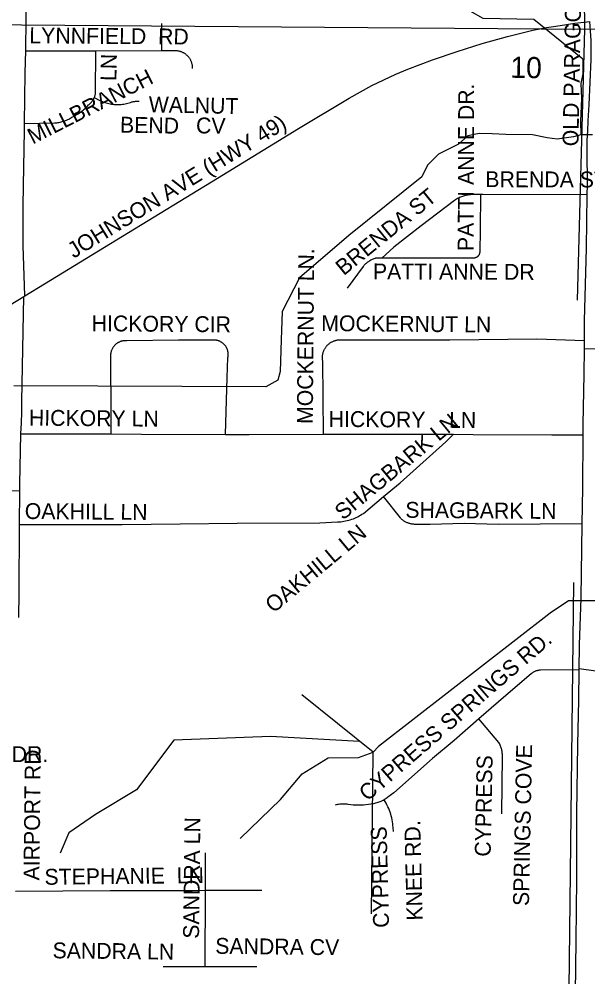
# Model space of a CAD drawing. Extents: x 1670563 to 1761545, y 515755 to 578944.
# Drawn here: x 1712453 to 1715137, y 555467 to 559991 of the extents above; entities that cross this region are included whole.
import ezdxf

# ---------------------------------------------------------------- set-up
doc = ezdxf.new("R2010")
doc.units = 0
for name, color, linetype in [('5_sectionlines', 7, 'Continuous'), ('62_text', 7, 'Continuous'), ('SHP_LINE', 7, 'Continuous'), ('STREETCL', 7, 'Continuous'), ('STRNAMES', 7, 'Continuous')]:
    doc.layers.add(name, color=color, linetype=linetype)

msp = doc.modelspace()

# ---------------------------------------------------------------- linework, layer by layer
at = {"layer": '5_sectionlines'}
msp.add_line((1715092.6, 565233.3), (1715121.2, 559943.8), dxfattribs=at)
for points in [[(1715121.2, 559943.8), (1720383.9, 560096.2), (1725635, 560117.2)], [(1677977.7, 559756.7), (1683296.8, 559793.9), (1688575.5, 559928.7), (1693867.8, 559919.3), (1699198.2, 559938), (1704504.6, 559990.6), (1709805, 559985.3), (1715121.2, 559943.8), (1715086.8, 558664.7)], [(1715069.2, 557329.6), (1715039, 554724.2), (1714928.9, 549450.5), (1714933.4, 546249.8)]]:
    msp.add_lwpolyline(points, dxfattribs=at)
at = {"layer": 'SHP_LINE'}
for points in [[(1715114, 559803), (1714883, 559990), (1714643, 559994), (1714582, 560029), (1714465, 560160), (1714343, 560203), (1714286, 560308), (1714194, 560386), (1713781, 560612)], [(1715114, 559803), (1715114, 559733), (1715105, 559688), (1715107, 559616), (1715103, 559510), (1715104, 559445)], [(1715159, 559445), (1715104, 559445), (1715069, 559435), (1714992, 559424), (1714945, 559431), (1714876, 559445), (1714751, 559446), (1714685, 559450), (1714625, 559452), (1714571, 559440), (1714527, 559401), (1714433, 559353), (1714381, 559302), (1714354, 559247), (1714009, 558970), (1713777, 558770), (1713695, 558610), (1713690, 558476), (1713685, 558327), (1713674, 558286), (1713618, 558255), (1712428, 558260)], [(1717283, 557390), (1716826, 557398), (1716048, 557390), (1715554, 557371), (1715449, 557349), (1715283, 557260), (1715184, 557243), (1715046, 557243), (1714960, 557185), (1714150, 556555), (1714124, 556528), (1713787, 556799)], [(1714060, 556579), (1713639, 556602), (1713183, 556586), (1713007, 556351), (1712814, 556234), (1712687, 556147), (1712647, 556052)], [(1713496, 556121), (1713687, 556305), (1713789, 556427), (1713911, 556502), (1714055, 556504), (1714124, 556528)], [(1714117, 555765), (1714124, 556528)]]:
    msp.add_lwpolyline(points, dxfattribs=at)
at = {"layer": 'STREETCL'}
for points in [[(1712484.1, 559841.9), (1712487, 559992.6), (1712487.7, 560069.5)], [(1712480.7, 558684.6), (1712572.9, 558740.6), (1712940.5, 558965.5), (1713388.6, 559240.4), (1713771.7, 559474.8), (1714010.2, 559617.7), (1714063.8, 559648.6), (1714118.5, 559677.9), (1714174, 559705.3), (1714230.4, 559730.9), (1714287.6, 559754.7), (1714403.4, 559798.6), (1714520.5, 559839.1), (1714638.7, 559876.1), (1714758, 559909.6), (1714878.2, 559939.6), (1714910.1, 559946.5), (1714942.2, 559952.4), (1714974.5, 559957.3), (1715007, 559961.1), (1715076.4, 559972.2), (1715146.1, 559980.9)], [(1713125.7, 559970.4), (1713125.7, 559843.2)], [(1715134.4, 559161.9), (1715135.1, 559208.4), (1715134.4, 559371.3), (1715134.8, 559417.8), (1715136.5, 559464.3), (1715139.4, 559510.7), (1715143.7, 559586.8), (1715153.1, 559800.7), (1715153.7, 559845.8), (1715152.7, 559890.9), (1715150.2, 559936), (1715146.1, 559980.9)], [(1712478.4, 559498.5), (1712482.1, 559737.8), (1712484.1, 559841.9)], [(1712484.1, 559841.9), (1712815.8, 559842.6)], [(1712807.7, 559620.8), (1712808.9, 559623.5), (1712809.9, 559626.3), (1712810.9, 559629.1), (1712811.8, 559631.9), (1712812.5, 559634.7), (1712813.2, 559637.6), (1712813.8, 559640.5), (1712814.3, 559643.4), (1712815.8, 559842.6)], [(1712815.8, 559842.6), (1713125.7, 559843.2)], [(1713125.7, 559843.2), (1713173.4, 559843.3), (1713190.6, 559843.3), (1713193.4, 559843.2), (1713196.2, 559843), (1713199, 559842.7), (1713201.8, 559842.3), (1713204.6, 559841.9), (1713207.3, 559841.3), (1713210.1, 559840.6), (1713212.8, 559839.8), (1713215.5, 559839), (1713218.1, 559838), (1713220.7, 559837), (1713223.3, 559835.8), (1713225.8, 559834.6), (1713228.3, 559833.3), (1713230.8, 559831.9), (1713233.2, 559830.4), (1713235.5, 559828.8), (1713237.8, 559827.2), (1713240, 559825.4), (1713242.2, 559823.6), (1713244.3, 559821.7), (1713246.3, 559819.8), (1713248.3, 559817.8), (1713250.2, 559815.7), (1713252, 559813.5), (1713253.7, 559811.3), (1713255.4, 559809), (1713257, 559806.7), (1713258.5, 559804.3), (1713259.9, 559801.9), (1713261.2, 559799.4), (1713262.5, 559796.9), (1713263.6, 559794.3), (1713264.7, 559791.7), (1713265.7, 559789.1), (1713266.6, 559786.4), (1713267.3, 559783.7), (1713268, 559780.9), (1713268.6, 559778.2), (1713269.1, 559775.4), (1713269.5, 559772.6), (1713269.8, 559769.8), (1713270, 559767), (1713270.2, 559764.2), (1713270.2, 559761.4), (1713270.1, 559758.6)], [(1712478.4, 559498.5), (1712619.5, 559501.7), (1712625, 559502), (1712630.4, 559502.4), (1712635.8, 559503.1), (1712641.1, 559503.9), (1712646.4, 559504.9), (1712651.7, 559506.1), (1712657, 559507.5), (1712662.2, 559509.1), (1712667.3, 559510.8), (1712672.4, 559512.7), (1712677.4, 559514.8), (1712682.3, 559517.1), (1712687.2, 559519.5), (1712691.9, 559522.1), (1712696.6, 559524.8), (1712701.2, 559527.7), (1712705.7, 559530.8), (1712712.2, 559533.9), (1712718.7, 559537.2), (1712725.1, 559540.7), (1712731.3, 559544.4), (1712737.5, 559548.3), (1712743.5, 559552.5), (1712749.3, 559556.8), (1712755, 559561.3), (1712760.6, 559565.9), (1712766, 559570.8), (1712771.2, 559575.8), (1712776.3, 559581.1), (1712781.2, 559586.4), (1712783.6, 559588.4), (1712786, 559590.5), (1712788.2, 559592.6), (1712790.4, 559594.9), (1712792.6, 559597.2), (1712794.6, 559599.6), (1712796.6, 559602), (1712798.4, 559604.5), (1712800.2, 559607.1), (1712801.9, 559609.7), (1712803.5, 559612.4), (1712805, 559615.2), (1712806.4, 559618), (1712807.7, 559620.8)], [(1712807.7, 559620.8), (1712834.2, 559607.6), (1712840, 559604.8), (1712845.9, 559602.2), (1712851.9, 559599.9), (1712858, 559597.7), (1712864.2, 559595.7), (1712870.4, 559594), (1712876.7, 559592.5), (1712883, 559591.2), (1712889.4, 559590.1), (1712895.8, 559589.2), (1712902.2, 559588.6), (1712908.7, 559588.2), (1712915.1, 559588), (1712921.6, 559588), (1712928.1, 559588.3), (1712934.5, 559588.8), (1712940.9, 559589.5), (1712947.3, 559590.4), (1712953.7, 559591.6), (1712960, 559592.9), (1712966.3, 559594.5), (1712972.5, 559596.3), (1712978.6, 559598.3), (1712981.9, 559599.4), (1712985.2, 559600.4), (1712988.6, 559601.3), (1712992, 559602), (1712995.4, 559602.6), (1712998.9, 559603.1), (1713002.3, 559603.5), (1713005.8, 559603.8), (1713009.3, 559603.9), (1713012.7, 559603.9), (1713016.2, 559603.8), (1713019.7, 559603.6)], [(1712480.7, 558684.6), (1712472.3, 558922.9), (1712471.6, 559107.2), (1712473.7, 559205.7), (1712477.9, 559464.8), (1712478.4, 559498.5)], [(1714632.8, 559162.9), (1714597.4, 559162.9), (1714592.1, 559162.8), (1714586.9, 559162.6), (1714581.6, 559162.1), (1714576.4, 559161.5), (1714571.2, 559160.7), (1714566, 559159.8), (1714560.9, 559158.6), (1714555.8, 559157.3), (1714550.8, 559155.9), (1714545.8, 559154.2), (1714540.8, 559152.4), (1714536, 559150.5), (1714531.1, 559148.3), (1714526.4, 559146.1), (1714521.8, 559143.6), (1714517.2, 559141), (1714512.7, 559138.3), (1714508.3, 559135.4), (1714350.6, 559014.4), (1714222.4, 558913.7), (1714164.7, 558862.4)], [(1714618.1, 558870.5), (1714618.9, 558871.2), (1714619.6, 558871.9), (1714620.4, 558872.7), (1714621.1, 558873.5), (1714621.8, 558874.3), (1714622.4, 558875.2), (1714623, 558876), (1714623.6, 558876.9), (1714624.2, 558877.8), (1714624.7, 558878.7), (1714625.2, 558879.7), (1714625.7, 558880.6), (1714626.2, 558881.6), (1714626.6, 558882.6), (1714626.9, 558883.6), (1714627.3, 558884.6), (1714627.6, 558885.6), (1714627.9, 558886.7), (1714628.1, 558887.7), (1714628.3, 558888.8), (1714628.5, 558889.8), (1714630.5, 558998.6), (1714632.8, 559162.9)], [(1715134.4, 559161.9), (1714642.2, 559162.9), (1714632.8, 559162.9)], [(1715121.6, 558473), (1715122.2, 558566.5), (1715130.8, 558909), (1715134.4, 559161.9)], [(1714164.7, 558862.8), (1714151.2, 558862.8), (1714149.3, 558862.9), (1714147.3, 558862.9), (1714145.4, 558862.9), (1714143.4, 558862.7), (1714141.5, 558862.6), (1714139.6, 558862.3), (1714137.7, 558862), (1714135.8, 558861.6), (1714133.9, 558861.2), (1714132, 558860.7), (1714128, 558859.3), (1714124, 558857.7), (1714120.1, 558856), (1714116.3, 558854.2), (1714112.5, 558852.3), (1714108.8, 558850.2), (1714105.2, 558848), (1714101.6, 558845.6), (1714098.1, 558843.1), (1714094.8, 558840.6), (1714091.5, 558837.9), (1714088.3, 558835.1), (1714085.2, 558832.1), (1714082.2, 558829.1), (1714079.3, 558826), (1714076.6, 558822.7), (1714001.3, 558721.1)], [(1714618.1, 558870.5), (1714617.3, 558869.8), (1714616.4, 558869.1), (1714615.6, 558868.5), (1714614.7, 558867.8), (1714613.8, 558867.3), (1714612.9, 558866.7), (1714612, 558866.2), (1714611, 558865.7), (1714610, 558865.2), (1714609.1, 558864.8), (1714608.1, 558864.4), (1714607.1, 558864.1), (1714606, 558863.8), (1714605, 558863.5), (1714604, 558863.2), (1714602.9, 558863), (1714601.9, 558862.8), (1714600.8, 558862.7), (1714599.8, 558862.5), (1714598.7, 558862.5), (1714597.6, 558862.4), (1714164.7, 558862.8)], [(1712308.9, 558580.2), (1712475.3, 558681.4)], [(1712461.9, 558032.9), (1712464, 558083.9), (1712465.8, 558134.3), (1712466.5, 558184.9), (1712475.3, 558681.4)], [(1712475.3, 558681.4), (1712480.7, 558684.6)], [(1713888.9, 558030.4), (1713885.9, 558378.1), (1713885.4, 558380.9), (1713885.1, 558383.8), (1713884.8, 558386.7), (1713884.7, 558389.6), (1713884.6, 558392.5), (1713884.6, 558395.4), (1713884.8, 558398.3), (1713885, 558401.2), (1713885.4, 558404.1), (1713885.8, 558407), (1713886.3, 558409.9), (1713887, 558412.7), (1713887.7, 558415.5), (1713888.6, 558418.3), (1713889.5, 558421), (1713890.5, 558423.8), (1713891.6, 558426.5), (1713892.8, 558429.1), (1713894.1, 558431.7), (1713895.5, 558434.3), (1713897, 558436.8), (1713898.6, 558439.2), (1713900.2, 558441.6), (1713901.9, 558443.9), (1713903.8, 558446.2), (1713905.6, 558448.4), (1713907.6, 558450.6), (1713909.6, 558452.7), (1713911.8, 558454.7), (1713913.9, 558456.6), (1713916.2, 558458.4), (1713918.5, 558460.2), (1713920.8, 558461.9), (1713923.3, 558463.5), (1713925.7, 558465.1), (1713928.3, 558466.5), (1713930.8, 558467.8), (1713933.4, 558469.1), (1713936.1, 558470.3), (1713938.8, 558471.4), (1713941.5, 558472.3), (1713944.3, 558473.2), (1713947.1, 558474), (1713949.9, 558474.7), (1713952.8, 558475.3), (1713955.7, 558475.8), (1713958.5, 558476.2), (1713961.4, 558476.5), (1713964.3, 558476.7), (1713967.2, 558476.8), (1713970.1, 558476.8), (1713973, 558476.7), (1713975.9, 558476.5), (1714486.7, 558476.5), (1714897.2, 558480.8), (1715121.6, 558473)], [(1713427, 558030.1), (1713435.2, 558298.7), (1713438.3, 558392.4), (1713438.8, 558394.7), (1713439.2, 558397), (1713439.6, 558399.3), (1713439.8, 558401.6), (1713440, 558404), (1713440.1, 558406.3), (1713440.1, 558408.6), (1713440, 558411), (1713439.9, 558413.3), (1713439.7, 558415.6), (1713439.3, 558417.9), (1713438.9, 558420.2), (1713438.5, 558422.5), (1713437.9, 558424.8), (1713437.3, 558427), (1713436.6, 558429.3), (1713435.8, 558431.5), (1713435, 558433.6), (1713434, 558435.8), (1713433, 558437.9), (1713431.9, 558440), (1713430.8, 558442), (1713429.6, 558444), (1713428.3, 558445.9), (1713426.9, 558447.8), (1713425.5, 558449.7), (1713424, 558451.5), (1713422.5, 558453.2), (1713420.9, 558454.9), (1713419.2, 558456.6), (1713417.5, 558458.2), (1713415.7, 558459.7), (1713413.9, 558461.1), (1713412, 558462.5), (1713410.1, 558463.9), (1713408.2, 558465.1), (1713406.1, 558466.3), (1713404.1, 558467.5), (1713402, 558468.5), (1713399.9, 558469.5), (1713397.7, 558470.4), (1713395.6, 558471.2), (1713393.4, 558472), (1713391.1, 558472.7), (1713388.9, 558473.3), (1713386.6, 558473.8), (1713384.3, 558474.2), (1713382, 558474.6), (1713379.7, 558474.9), (1713377.3, 558475.1), (1713375, 558475.2), (1713372.7, 558475.2), (1713205.4, 558475.2), (1712961.5, 558472.1), (1712959.1, 558472.3), (1712956.7, 558472.4), (1712954.2, 558472.4), (1712951.8, 558472.3), (1712949.4, 558472.2), (1712947, 558471.9), (1712944.6, 558471.6), (1712942.2, 558471.2), (1712939.8, 558470.7), (1712937.5, 558470.2), (1712935.1, 558469.5), (1712932.8, 558468.8), (1712930.5, 558468), (1712928.3, 558467.1), (1712926.1, 558466.2), (1712923.9, 558465.1), (1712921.7, 558464), (1712919.6, 558462.8), (1712917.5, 558461.6), (1712915.5, 558460.2), (1712913.5, 558458.9), (1712911.6, 558457.4), (1712909.7, 558455.9), (1712907.9, 558454.3), (1712906.1, 558452.6), (1712904.4, 558450.9), (1712902.8, 558449.1), (1712901.2, 558447.3), (1712899.6, 558445.4), (1712898.2, 558443.5), (1712896.8, 558441.5), (1712895.5, 558439.5), (1712894.2, 558437.4), (1712893, 558435.3), (1712891.9, 558433.2), (1712890.9, 558431), (1712889.9, 558428.7), (1712889, 558426.5), (1712888.2, 558424.2), (1712887.5, 558421.9), (1712886.8, 558419.6), (1712886.3, 558417.2), (1712885.8, 558414.8), (1712885.4, 558412.5), (1712885.1, 558410.1), (1712884.8, 558407.6), (1712884.7, 558405.2), (1712884.6, 558402.8), (1712884.6, 558400.4), (1712884.7, 558398), (1712884.9, 558395.5), (1712886.5, 558115.8), (1712886.5, 558031.7)], [(1715115.3, 558028.2), (1715115.7, 558077), (1715120.7, 558313.8), (1715121.4, 558433.8)], [(1715121.4, 558433.8), (1715121.6, 558473)], [(1715422, 558431), (1715346.3, 558431.9), (1715121.4, 558433.8)], [(1712456.1, 557761.2), (1712456.4, 557794.1), (1712461.9, 558032.9)], [(1712461.9, 558032.9), (1712886.5, 558031.7)], [(1712886.5, 558031.7), (1713030.7, 558031.3), (1713427, 558030.1)], [(1713427, 558030.1), (1713539.4, 558029.8), (1713888.9, 558030.4)], [(1713888.9, 558030.4), (1714304.7, 558031.2), (1714503, 558030.2)], [(1714172.9, 557736), (1714251.4, 557801.5), (1714467.3, 557994.5), (1714503, 558030.2)], [(1714503, 558030.2), (1714595.8, 558029.7), (1714966.7, 558028.2), (1715115.3, 558028.2)], [(1715111, 557607.9), (1715113.5, 557776.2), (1715115.3, 558028.2)], [(1712456.1, 557761.2), (1712217.8, 557767.4)], [(1712455, 557604.6), (1712456.1, 557761.2)], [(1712455, 557604.6), (1712939.6, 557604.6), (1713213.3, 557607.5), (1713481.6, 557610.5), (1713872.1, 557612), (1713955.8, 557616.6), (1713963.4, 557616.9), (1713971.1, 557617.5), (1713978.7, 557618.3), (1713986.2, 557619.4), (1713993.8, 557620.8), (1714001.3, 557622.4), (1714008.7, 557624.3), (1714016, 557626.4), (1714023.3, 557628.8), (1714030.5, 557631.4), (1714037.6, 557634.3), (1714044.6, 557637.4), (1714051.5, 557640.8), (1714058.2, 557644.4), (1714064.8, 557648.2), (1714071.3, 557652.3), (1714077.7, 557656.6), (1714172.9, 557736)], [(1715111, 557607.9), (1714713.3, 557604.7), (1714554.1, 557609.3), (1714393.4, 557604.7), (1714322.2, 557604.7), (1714318.9, 557604.8), (1714315.6, 557605), (1714312.4, 557605.2), (1714309.2, 557605.6), (1714305.9, 557606.1), (1714302.7, 557606.7), (1714299.6, 557607.5), (1714296.4, 557608.3), (1714293.3, 557609.2), (1714290.2, 557610.2), (1714287.2, 557611.4), (1714284.1, 557612.6), (1714281.2, 557614), (1714278.3, 557615.4), (1714275.4, 557617), (1714272.6, 557618.6), (1714269.8, 557620.4), (1714267.1, 557622.2), (1714264.5, 557624.1), (1714261.9, 557626.1), (1714259.4, 557628.2), (1714257, 557630.4), (1714254.7, 557632.7), (1714252.4, 557635), (1714172.9, 557736)], [(1712451.6, 557165), (1712452.6, 557279.4), (1712455, 557604.6)], [(1715096.4, 556918.2), (1715098.4, 557035.6), (1715106.3, 557258.1), (1715109.2, 557489.7), (1715111, 557607.9)], [(1715096.4, 556918.2), (1714914.5, 556915.9), (1714912.1, 556915.8), (1714909.7, 556915.6), (1714907.3, 556915.4), (1714904.9, 556915.1), (1714902.6, 556914.7), (1714900.2, 556914.2), (1714897.9, 556913.6), (1714895.5, 556913), (1714893.2, 556912.3), (1714891, 556911.5), (1714888.7, 556910.6), (1714886.5, 556909.7), (1714884.3, 556908.6), (1714882.2, 556907.5), (1714880.1, 556906.4), (1714878, 556905.1), (1714876, 556903.8), (1714874, 556902.5), (1714872.1, 556901), (1714715.1, 556766.3), (1714623.6, 556686.4)], [(1715075.9, 554748.6), (1715075.4, 554831.9), (1715076.1, 555142), (1715079, 555389.6), (1715081.9, 555638.7), (1715084.7, 555928), (1715084.7, 556004.8), (1715085.4, 556241), (1715090.5, 556564.9), (1715094.1, 556774.3), (1715096.4, 556918.2)], [(1715096.5, 556924.3), (1715432.6, 556877.4)], [(1714623.6, 556686.4), (1714505.7, 556583.4), (1714403.8, 556498.5), (1714220.9, 556335.9), (1714194, 556315.4), (1714189.5, 556312.1), (1714184.9, 556309), (1714180.1, 556306), (1714175.3, 556303.1)], [(1714731.4, 556237.2), (1714734.5, 556510.1), (1714734.4, 556514.5), (1714734.1, 556518.9), (1714733.7, 556523.3), (1714733.2, 556527.7), (1714732.5, 556532.1), (1714731.6, 556536.5), (1714730.6, 556540.8), (1714729.5, 556545.1), (1714728.2, 556549.3), (1714726.8, 556553.5), (1714725.3, 556557.7), (1714723.6, 556561.8), (1714721.8, 556565.8), (1714719.9, 556569.8), (1714717.8, 556573.7), (1714623.6, 556686.4)], [(1714175.3, 556303.1), (1714170.6, 556300.6), (1714165.8, 556298.2), (1714160.9, 556295.9), (1714155.9, 556293.8), (1714150.9, 556291.9), (1714145.8, 556290.1), (1714140.7, 556288.5), (1714135.5, 556287.1), (1714130.3, 556285.8), (1714125, 556284.7), (1714113.3, 556282.6), (1714101.4, 556280.9), (1714089.6, 556279.7), (1714077.7, 556278.8), (1714065.7, 556278.2), (1714053.8, 556278.1), (1714041.9, 556278.4), (1714029.9, 556279), (1714018, 556280.1), (1714006.2, 556281.5), (1714000.6, 556282.2), (1713995, 556282.6), (1713989.3, 556282.9), (1713983.7, 556283), (1713978.1, 556282.9), (1713972.5, 556282.6), (1713966.8, 556282.2), (1713961.2, 556281.5), (1713955.7, 556280.6), (1713950.1, 556279.6), (1713944.6, 556278.3)], [(1714219.5, 556153.2), (1714218.4, 556172.3), (1714217.7, 556181.5), (1714216.7, 556190.8), (1714215.4, 556200), (1714213.8, 556209.1), (1714211.8, 556218.2), (1714209.5, 556227.2), (1714206.9, 556236.1), (1714204, 556245), (1714200.8, 556253.7), (1714197.3, 556262.3), (1714193.4, 556270.7), (1714189.3, 556279.1), (1714184.9, 556287.3), (1714180.3, 556295.3), (1714175.3, 556303.1)], [(1713333.4, 555876.1), (1713333.4, 556015.6), (1713333.4, 556053.6)], [(1712435.5, 555872.5), (1712882.7, 555875), (1713269.1, 555875.8), (1713333.4, 555876.1)], [(1713331.9, 555876.1), (1713329.2, 555516.3)], [(1713333.4, 555876.1), (1713599, 555877.3)], [(1713132.9, 555515.9), (1713329.2, 555516.3)], [(1713329.2, 555516.3), (1713574.6, 555516.7)]]:
    msp.add_lwpolyline(points, dxfattribs=at)

# ---------------------------------------------------------------- texts
at = {"layer": '62_text'}
msp.add_text('10', height=100, rotation=358.9284, dxfattribs=at).set_placement((1714770.6, 559714.7))
at = {"layer": 'STRNAMES'}
for s, rotation, p in [('OLD PARAGOULD HWY', 88.9419, (1715092.8, 559390.3)), ('LYNNFIELD  RD', 359.5288, (1712501.2, 559877.6)), ('LN', 88.8242, (1712911.9, 559698.6)), ('MILLBRANCH', 26.9896, (1712517.2, 559398.6)), ('PATTI ANNE DR.', 89.8288, (1714598.2, 558895.8)), ('WALNUT ', 358.8242, (1713064, 559551.8)), ('JOHNSON AVE (HWY 49)', 31.5505, (1712711, 558859.3)), ('BEND ', 358.8242, (1712928.6, 559455.9)), ('CV', 358.8242, (1713287.4, 559452.4)), ('BRENDA ST.', 359.8288, (1714653.3, 559197.9)), ('BRENDA ST', 39.2108, (1713985.2, 558777)), ('MOCKERNUT LN.', 89.5288, (1713839, 558078.9)), ('PATTI ANNE DR', 359.8288, (1714122.9, 558762.2)), ('HICKORY CIR', 359.5288, (1712795.2, 558517.4)), ('MOCKERNUT LN', 359.5288, (1713878.9, 558518)), ('HICKORY LN', 359.5288, (1712498.9, 558071.4)), ('HICKORY    LN', 359.5288, (1713913.8, 558065.6)), ('SHAGBARK LN', 39.5401, (1713981.7, 557621.8)), ('SHAGBARK LN', 359.5288, (1714275.8, 557636)), ('OAKHILL LN', 359.5288, (1712479.4, 557630.3)), ('OAKHILL LN', 39.7406, (1713653.8, 557182.6)), ('CYPRESS SPRINGS RD.', 40.8353, (1714097.5, 556293.6)), ('BURDYSHAW  DR.', 0.2227, (1711710.5, 556478.6)), ('AIRPORT RD', 89.3686, (1712548.5, 555922.5)), ('SPRINGS COVE', 88.8227, (1714859, 555801.5)), ('CYPRESS ', 88.8227, (1714678.4, 556034.3)), ('SANDRA LN', 89.3227, (1713302, 555647.1)), ('CYPRESS', 91.4272, (1714199.3, 555699.7)), (' KNEE RD.', 91.4272, (1714358.4, 555706.1)), ('STEPHANIE  LN', 0.6334, (1712573.2, 555901.9)), ('SANDRA LN', 359.3227, (1712610.6, 555555)), ('SANDRA CV', 359.3227, (1713378.4, 555576.2))]:
    msp.add_text(s, height=75, rotation=rotation, dxfattribs=at).set_placement(p)

doc.saveas('drawing.dxf')
